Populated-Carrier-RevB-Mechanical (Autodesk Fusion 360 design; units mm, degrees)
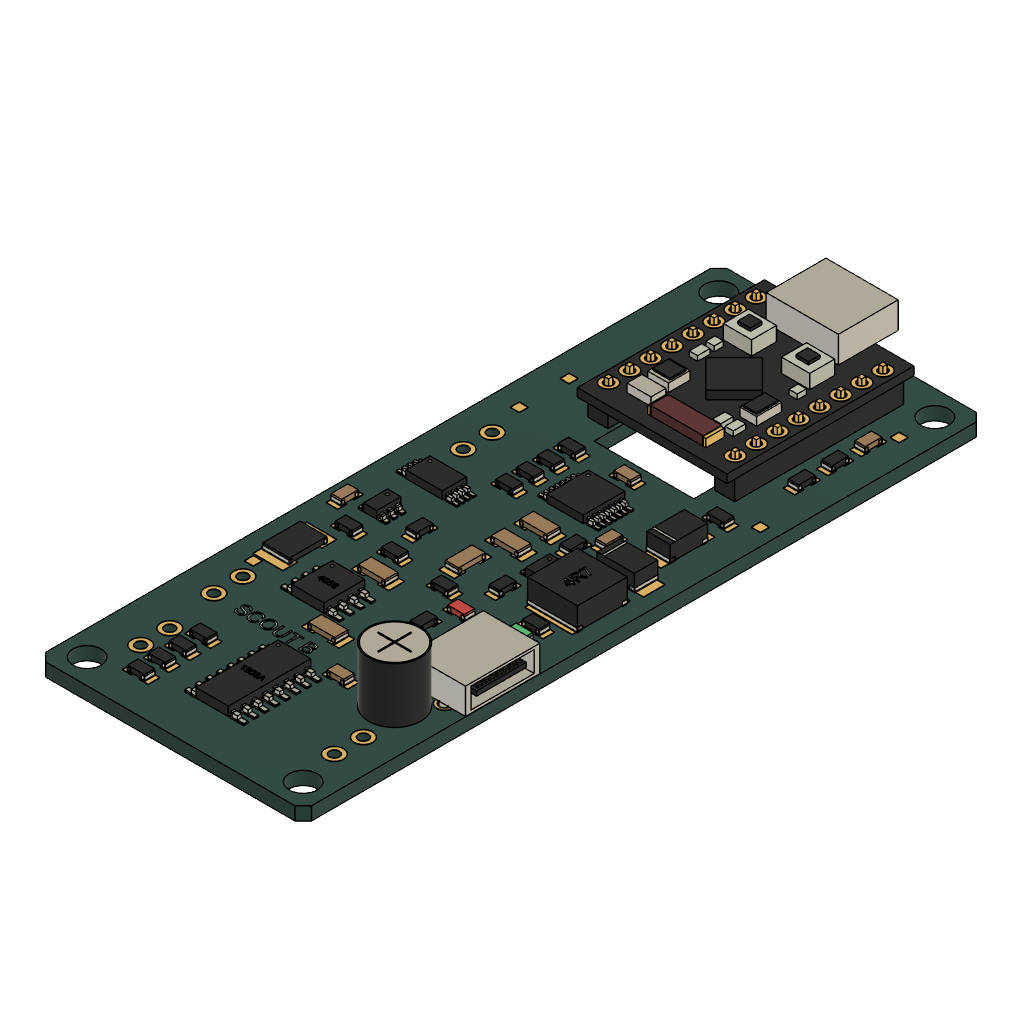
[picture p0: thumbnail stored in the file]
named bodies: "Body1", "Body2", "Body3", "Body4", "Body5", "Body6", "Body7", "Body8", "Body9", "Body10", "Body11", "Body12", "Body13", "Body14", "Body15", "Body16", "Body17", "Body18", "Body19", "Body20", "Body21", "Body22", "Body23", "Body24", "Body25", "Body26", "Body27", "Body28", "Body29", "Body30", "Body31", "Body32", "Body33", "Body34", "Body35", "Body36", "Body37", "Body38", "Body39", "Body40", "Body41", "Body42", "Body43", "Body44", "Body45", "Body46", "Body47", "Body48", "Body49", "Body50", "Body51", "Body52", "Body53", "Body54", "Body55", "Body56", "Body57", "Body58", "Body59", "Body60"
